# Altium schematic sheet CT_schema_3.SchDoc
size 360 x 214 mm
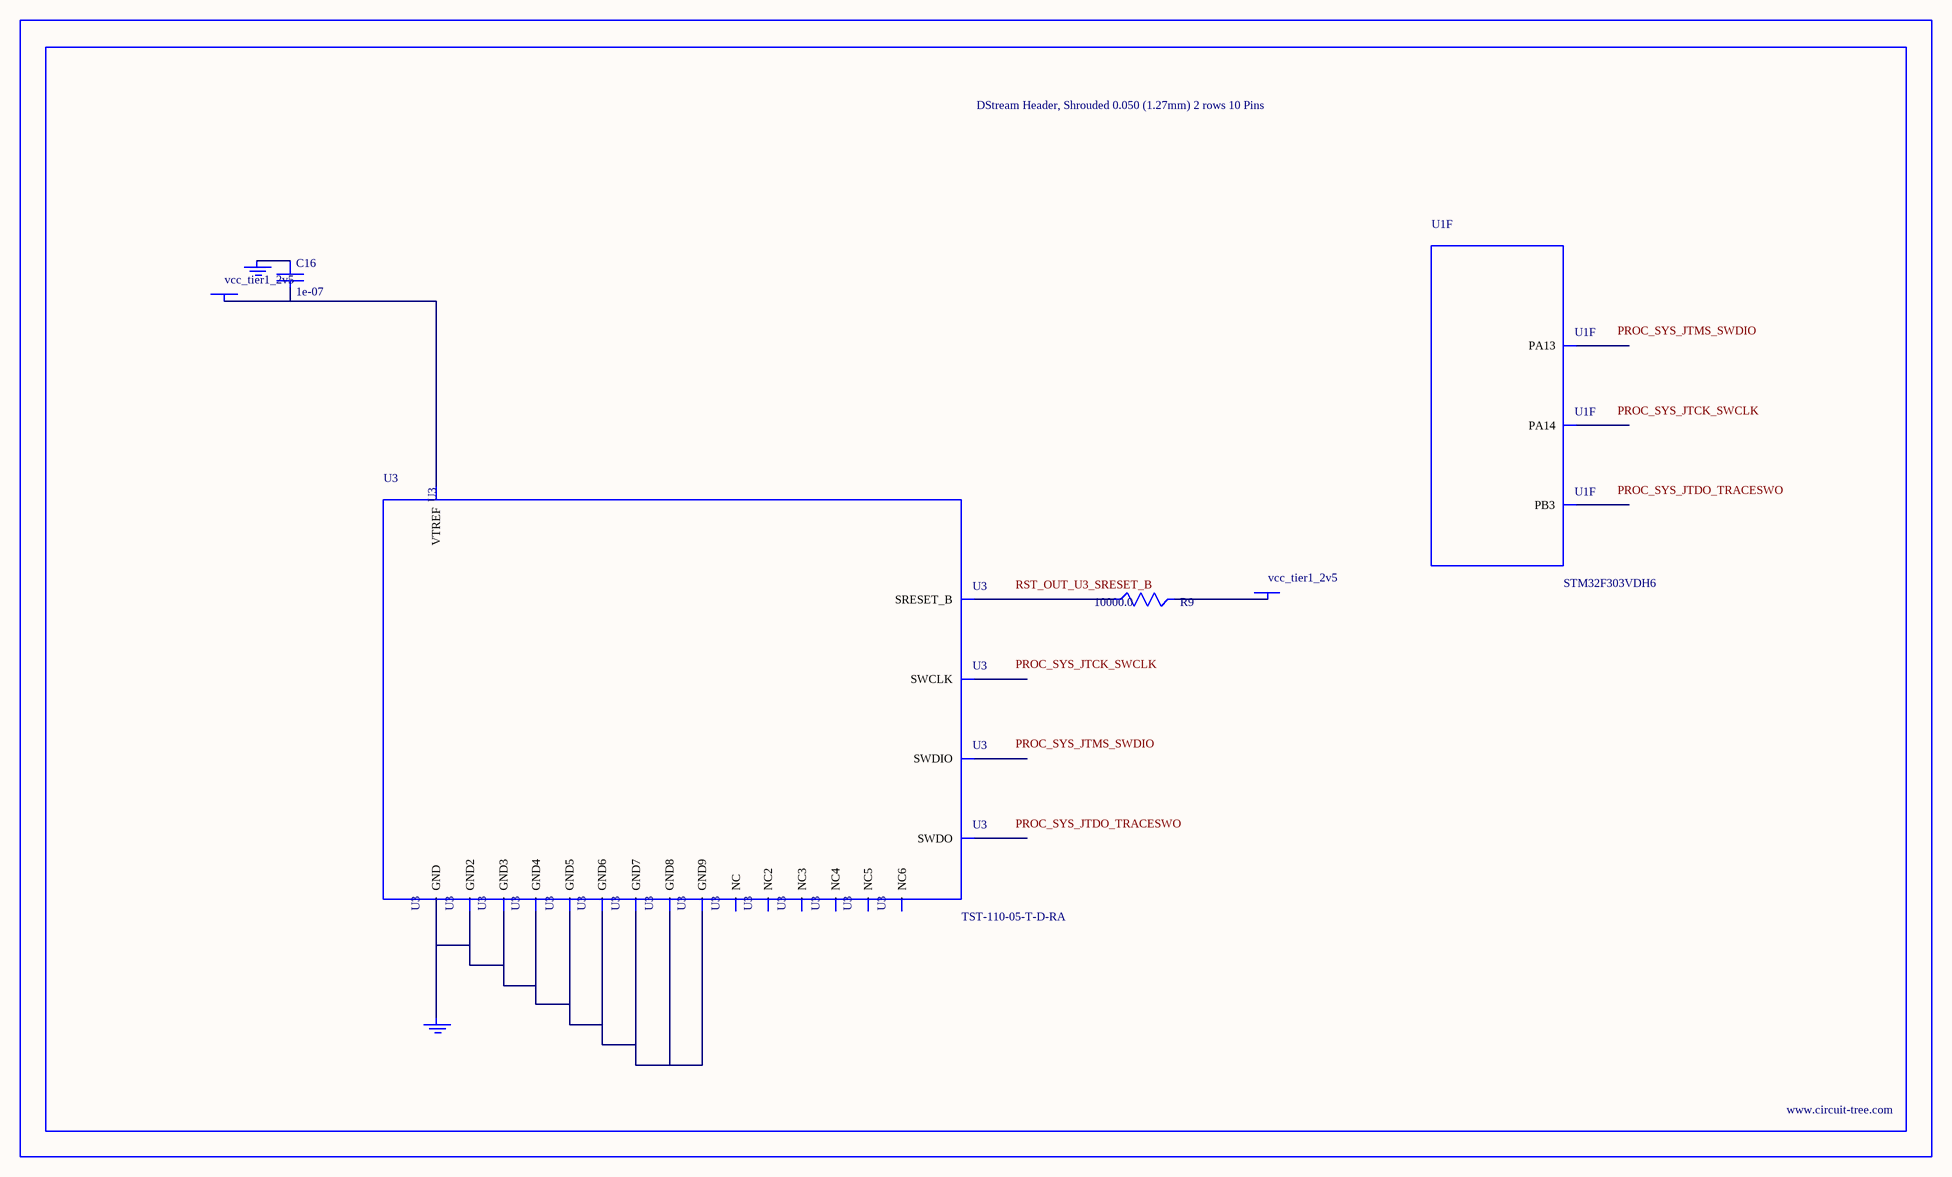
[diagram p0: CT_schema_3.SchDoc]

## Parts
BORDER2  (no value)
C16  1e-07  [C0402]
GND_INSTANCE_2_0  (no value)
GND_INSTANCE_2_1  (no value)
POWER_INSTANCE_2_0  vcc_tier1_2v5
POWER_INSTANCE_2_1  vcc_tier1_2v5
R9  10000.0  [R0603]
U1  STM32F303VDH6  [UFBGA100]  (part F of 8)
U3  TST-110-05-T-D-RA  [TST-110-05-T-D-RA]

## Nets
NetC16_1: C16.1 GND_INSTANCE_2_0.0(GND)
NetC16_2: C16.2 POWER_INSTANCE_2_0.0(PWR) U3.1(VTREF)
NetGND_INSTANCE_2_1_0: GND_INSTANCE_2_1.0(GND) U3.4(GND) U3.6(GND2) U3.8(GND3) U3.10(GND4) U3.12(GND5) U3.14(GND6) U3.16(GND7) U3.18(GND8) U3.20(GND9)
NetPOWER_INSTANCE_2_1_0: POWER_INSTANCE_2_1.0(PWR) R9.2
NetR9_1: R9.1 U3.15(SRESET_B)

Not connected (* = marked no-connect by the designer): U1 A8(PB3) A10(PA14) A11(PA13); U3 2(NC) 3(NC2) 5(NC3) 7(SWDIO) 9(SWCLK) 11(NC4) 13(SWDO) 17(NC5) 19(NC6)

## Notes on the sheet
- Labels drawn without touching a wire or pin: PROC_SYS_JTCK_SWCLK, PROC_SYS_JTDO_TRACESWO, PROC_SYS_JTMS_SWDIO, RST_OUT_U3_SRESET_B

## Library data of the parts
BORDER2 = BORDER_PAGE2
C16 = C0402C104K3RACTU
GND_INSTANCE_2_0 GND_INSTANCE_2_1 = GND
POWER_INSTANCE_2_0 POWER_INSTANCE_2_1 = PWR
R9 = RC0603JR-0710KL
